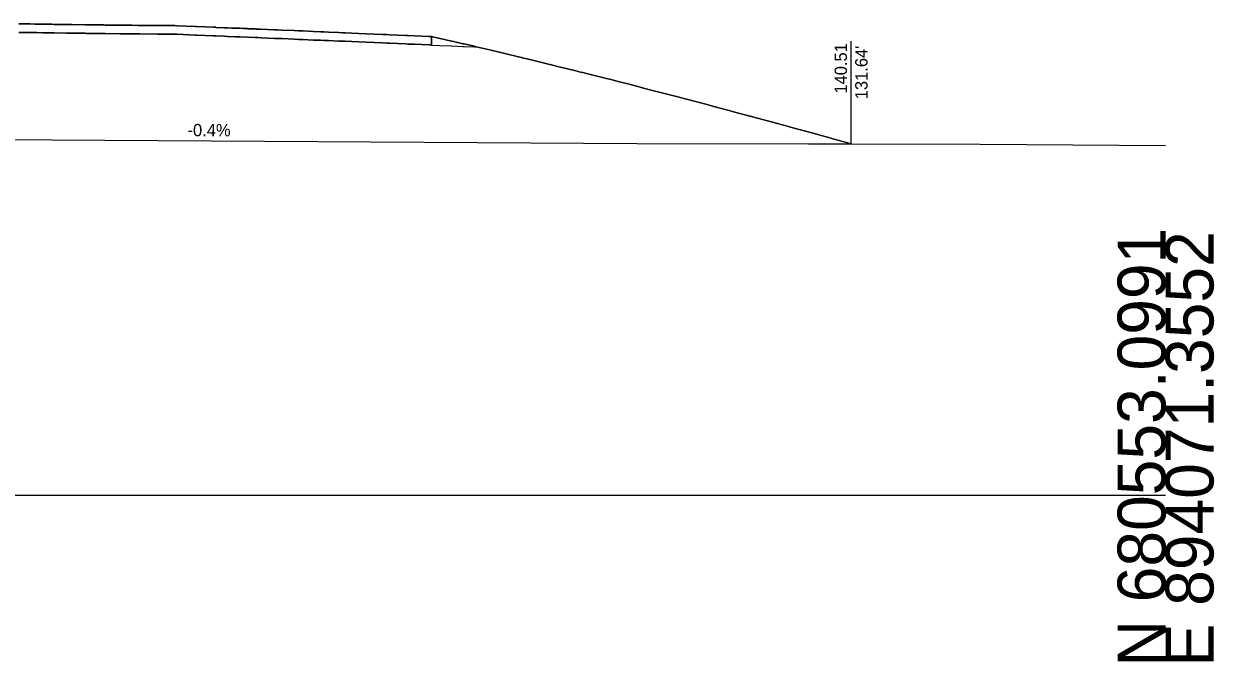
# Model space of a CAD drawing. Extents: x -26 to 4403, y -13 to 9578.
# Drawn here: x 1333.4 to 1402.8, y 7490.3 to 7527.5 of the extents above; entities that cross this region are included whole.
import ezdxf

# ---------------------------------------------------------------- set-up
doc = ezdxf.new("R2010")
doc.units = 0
for name, color, linetype in [('CONST_LV3', 7, 'Continuous'), ('DTM_P_FINISHED_GRADE', 7, 'Continuous'), ('DTM_X_GROUND', 7, 'Continuous'), ('X_PROFILES_1', 7, 'Continuous'), ('XS_CELL', 7, 'Continuous'), ('XS_M_SHAPES_EARTHWORK', 7, 'Continuous'), ('XS_P_DR_GRAVEL', 7, 'Continuous'), ('XS_P_GROUND', 7, 'Continuous'), ('XS_P_TX_CLEARZONE', 7, 'Continuous'), ('XS_P_TX_FS_BS', 7, 'Continuous')]:
    doc.layers.add(name, color=color, linetype=linetype)

msp = doc.modelspace()

# ---------------------------------------------------------------- linework, layer by layer
at = {"layer": 'CONST_LV3'}
msp.add_lwpolyline([(1333.065, 7527.511), (1333.712, 7527.501), (1333.992, 7527.496), (1334.096, 7527.494), (1334.782, 7527.485), (1334.979, 7527.481), (1335.338, 7527.477), (1335.483, 7527.474), (1335.854, 7527.469), (1335.978, 7527.467), (1336.156, 7527.464), (1336.927, 7527.455), (1336.991, 7527.454), (1337.184, 7527.451), (1338, 7527.442), (1338.018, 7527.442), (1338.107, 7527.44), (1338.989, 7527.431), (1339.061, 7527.43), (1339.075, 7527.43), (1340.031, 7527.421), (1340.131, 7527.42), (1340.148, 7527.42), (1340.642, 7527.415), (1340.7, 7527.415), (1341.204, 7527.411), (1341.221, 7527.411), (1342.167, 7527.404), (1342.294, 7527.399), (1342.297, 7527.399), (1342.298, 7527.398), (1342.301, 7527.398), (1343.364, 7527.354), (1343.416, 7527.352), (1343.438, 7527.352), (1344.433, 7527.31), (1344.558, 7527.305), (1344.576, 7527.305), (1345.5, 7527.266), (1345.715, 7527.257), (1345.724, 7527.257), (1346.164, 7527.238), (1346.423, 7527.227), (1346.853, 7527.209), (1346.915, 7527.207), (1347.013, 7527.203), (1347.186, 7527.196), (1347.991, 7527.161), (1348.135, 7527.155), (1348.413, 7527.144), (1349.128, 7527.113), (1349.384, 7527.103), (1349.641, 7527.092), (1350.264, 7527.065), (1350.665, 7527.048), (1350.872, 7527.04), (1351.398, 7527.017), (1351.981, 7526.993), (1352.103, 7526.988), (1352.326, 7526.978), (1352.719, 7526.962), (1352.915, 7526.953), (1353.333, 7526.935), (1354.298, 7526.893), (1354.566, 7526.881), (1354.725, 7526.876), (1355.655, 7526.835), (1355.797, 7526.829), (1356.159, 7526.814), (1357.015, 7526.777), (1357.028, 7526.776), (1357.154, 7526.771)], dxfattribs=at)
at = {"layer": 'DTM_P_FINISHED_GRADE'}
msp.add_lwpolyline([(1333.067, 7527.511), (1333.712, 7527.501), (1333.992, 7527.496), (1333.995, 7527.496), (1334.099, 7527.494), (1334.435, 7527.489), (1334.636, 7527.486), (1334.979, 7527.481), (1334.982, 7527.481), (1335.129, 7527.479), (1335.854, 7527.469), (1335.978, 7527.467), (1335.981, 7527.467), (1336.159, 7527.464), (1336.927, 7527.455), (1336.991, 7527.454), (1336.994, 7527.454), (1337.187, 7527.451), (1338.001, 7527.442), (1338.018, 7527.442), (1338.022, 7527.442), (1338.111, 7527.44), (1338.989, 7527.431), (1339.061, 7527.43), (1339.065, 7527.43), (1339.078, 7527.43), (1339.544, 7527.425), (1339.662, 7527.424), (1340.131, 7527.42), (1340.134, 7527.42), (1340.152, 7527.42), (1341.165, 7527.411), (1341.204, 7527.411), (1341.208, 7527.411), (1341.225, 7527.411), (1342.167, 7527.404), (1342.294, 7527.399), (1342.297, 7527.399), (1342.298, 7527.398), (1342.302, 7527.398), (1342.305, 7527.398), (1343.364, 7527.354), (1343.417, 7527.352), (1343.42, 7527.352), (1343.442, 7527.351), (1344.433, 7527.31), (1344.558, 7527.305), (1344.562, 7527.305), (1344.58, 7527.304), (1345.057, 7527.284), (1345.248, 7527.277), (1345.715, 7527.257), (1345.724, 7527.257), (1345.727, 7527.256), (1345.965, 7527.247), (1346.853, 7527.209), (1346.915, 7527.207), (1346.919, 7527.207), (1347.017, 7527.203), (1347.189, 7527.195), (1347.991, 7527.161), (1348.135, 7527.155), (1348.138, 7527.155), (1348.416, 7527.144), (1349.128, 7527.113), (1349.384, 7527.103), (1349.387, 7527.103), (1349.644, 7527.092), (1350.264, 7527.065), (1350.665, 7527.048), (1350.668, 7527.048), (1350.874, 7527.04), (1351.148, 7527.028), (1351.738, 7527.003), (1351.981, 7526.993), (1351.983, 7526.992), (1352.105, 7526.988), (1352.505, 7526.971), (1352.915, 7526.953), (1353.333, 7526.935), (1353.335, 7526.935), (1354.299, 7526.893), (1354.566, 7526.881), (1354.725, 7526.876), (1354.726, 7526.875), (1355.655, 7526.835), (1355.797, 7526.829), (1356.159, 7526.814), (1356.159, 7526.814), (1357.015, 7526.777), (1357.028, 7526.776), (1357.154, 7526.771)], dxfattribs=at)
at = {"layer": 'DTM_X_GROUND'}
msp.add_lwpolyline([(1159.518, 7517.394), (1200.052, 7515.401), (1217.74, 7513.76), (1222.892, 7513.417), (1226.763, 7513.627), (1241.699, 7515.779), (1244.696, 7517.139), (1249.906, 7516.828), (1249.956, 7516.833), (1276.709, 7519.611), (1283.124, 7519.79), (1294.202, 7520.766), (1295.632, 7520.835), (1310.279, 7520.767), (1331.863, 7520.749), (1369.14, 7520.527), (1389.173, 7520.495), (1400, 7520.407)], dxfattribs=at)
at = {"layer": 'XS_CELL'}
msp.add_line((1250, 7500), (1400, 7500), dxfattribs=at)
at = {"layer": 'XS_M_SHAPES_EARTHWORK'}
msp.add_lwpolyline([(1331.863, 7520.749), (1369.14, 7520.527), (1381.644, 7520.507), (1380.44, 7520.839), (1380.41, 7520.848), (1379.765, 7521.027), (1379.638, 7521.062), (1378.027, 7521.502), (1377.985, 7521.513), (1377.708, 7521.589), (1377.423, 7521.667), (1375.888, 7522.083), (1375.77, 7522.114), (1375.737, 7522.122), (1375.52, 7522.182), (1374.782, 7522.38), (1374.533, 7522.448), (1373.848, 7522.631), (1373.741, 7522.658), (1373.697, 7522.67), (1373.161, 7522.813), (1372.033, 7523.11), (1371.874, 7523.152), (1371.605, 7523.222), (1371.071, 7523.362), (1370.287, 7523.565), (1369.982, 7523.645), (1369.605, 7523.741), (1369.122, 7523.866), (1368.607, 7523.998), (1368.125, 7524.121), (1367.69, 7524.232), (1367.296, 7524.331), (1366.986, 7524.409), (1366.519, 7524.528), (1366.197, 7524.608), (1365.985, 7524.662), (1365.852, 7524.695), (1365.581, 7524.762), (1365.422, 7524.801), (1364.516, 7525.027), (1364.086, 7525.132), (1364.033, 7525.145), (1363.91, 7525.174), (1362.809, 7525.445), (1362.446, 7525.533), (1362.432, 7525.536), (1362.387, 7525.546), (1361.275, 7525.815), (1361.029, 7525.873), (1360.699, 7525.949), (1360.638, 7525.963), (1359.768, 7526.17), (1359.654, 7526.197), (1359.112, 7526.321), (1359.06, 7526.333), (1358.988, 7526.349), (1358.982, 7526.351), (1358.355, 7526.498), (1358.32, 7526.506), (1357.654, 7526.658), (1357.639, 7526.662), (1357.154, 7526.771), (1357.154, 7526.271), (1357.028, 7526.276), (1357.015, 7526.277), (1356.159, 7526.314), (1355.797, 7526.329), (1355.655, 7526.335), (1354.725, 7526.376), (1354.566, 7526.381), (1354.299, 7526.393), (1353.335, 7526.435), (1353.333, 7526.435), (1352.915, 7526.453), (1352.505, 7526.471), (1352.105, 7526.488), (1351.983, 7526.492), (1351.981, 7526.493), (1351.738, 7526.503), (1351.148, 7526.528), (1350.874, 7526.54), (1350.668, 7526.548), (1350.665, 7526.548), (1350.264, 7526.565), (1349.644, 7526.592), (1349.387, 7526.603), (1349.384, 7526.603), (1349.128, 7526.613), (1348.416, 7526.644), (1348.138, 7526.655), (1348.135, 7526.655), (1347.991, 7526.661), (1347.189, 7526.695), (1347.017, 7526.703), (1346.919, 7526.707), (1346.915, 7526.707), (1346.853, 7526.709), (1345.965, 7526.747), (1345.727, 7526.756), (1345.724, 7526.757), (1345.715, 7526.757), (1345.248, 7526.777), (1345.057, 7526.784), (1344.58, 7526.804), (1344.562, 7526.805), (1344.558, 7526.805), (1344.433, 7526.81), (1343.442, 7526.851), (1343.42, 7526.852), (1343.417, 7526.852), (1343.364, 7526.854), (1342.305, 7526.898), (1342.302, 7526.898), (1342.297, 7526.899), (1342.294, 7526.899), (1342.167, 7526.904), (1341.225, 7526.911), (1341.208, 7526.911), (1341.204, 7526.911), (1341.165, 7526.911), (1340.152, 7526.92), (1340.134, 7526.92), (1340.131, 7526.92), (1339.662, 7526.924), (1339.544, 7526.925), (1339.078, 7526.93), (1339.065, 7526.93), (1339.061, 7526.93), (1338.989, 7526.931), (1338.111, 7526.94), (1338.022, 7526.942), (1338.018, 7526.942), (1338.001, 7526.942), (1337.187, 7526.951), (1336.994, 7526.954), (1336.991, 7526.954), (1336.927, 7526.955), (1336.159, 7526.964), (1335.981, 7526.967), (1335.978, 7526.967), (1335.854, 7526.969), (1335.129, 7526.979), (1334.982, 7526.981), (1334.979, 7526.981), (1334.636, 7526.986), (1334.435, 7526.989), (1334.099, 7526.994), (1333.995, 7526.996), (1333.992, 7526.996), (1333.712, 7527.001), (1333.067, 7527.011)], dxfattribs=at)
at = {"layer": 'XS_P_DR_GRAVEL'}
for points in [[(1333.067, 7527.011), (1333.712, 7527.001), (1333.992, 7526.996), (1333.995, 7526.996), (1334.099, 7526.994), (1334.435, 7526.989), (1334.636, 7526.986), (1334.979, 7526.981), (1334.982, 7526.981), (1335.129, 7526.979), (1335.854, 7526.969), (1335.978, 7526.967), (1335.981, 7526.967), (1336.159, 7526.964), (1336.927, 7526.955), (1336.991, 7526.954), (1336.994, 7526.954), (1337.187, 7526.951), (1338.001, 7526.942), (1338.018, 7526.942), (1338.022, 7526.942), (1338.111, 7526.94), (1338.989, 7526.931), (1339.061, 7526.93), (1339.065, 7526.93), (1339.078, 7526.93), (1339.544, 7526.925), (1339.662, 7526.924), (1340.131, 7526.92), (1340.134, 7526.92), (1340.152, 7526.92), (1341.165, 7526.911), (1341.204, 7526.911), (1341.208, 7526.911), (1341.225, 7526.911), (1342.167, 7526.904), (1342.294, 7526.899), (1342.297, 7526.899), (1342.298, 7526.898), (1342.302, 7526.898), (1342.305, 7526.898), (1343.364, 7526.854), (1343.417, 7526.852), (1343.42, 7526.852), (1343.442, 7526.851), (1344.433, 7526.81), (1344.558, 7526.805), (1344.562, 7526.805), (1344.58, 7526.804), (1345.057, 7526.784), (1345.248, 7526.777), (1345.715, 7526.757), (1345.724, 7526.757), (1345.727, 7526.756), (1345.965, 7526.747), (1346.853, 7526.709), (1346.915, 7526.707), (1346.919, 7526.707), (1347.017, 7526.703), (1347.189, 7526.695), (1347.991, 7526.661), (1348.135, 7526.655), (1348.138, 7526.655), (1348.416, 7526.644), (1349.128, 7526.613), (1349.384, 7526.603), (1349.387, 7526.603), (1349.644, 7526.592), (1350.264, 7526.565), (1350.665, 7526.548), (1350.668, 7526.548), (1350.874, 7526.54), (1351.148, 7526.528), (1351.738, 7526.503), (1351.981, 7526.493), (1351.983, 7526.492), (1352.105, 7526.488), (1352.505, 7526.471), (1352.915, 7526.453), (1353.333, 7526.435), (1353.335, 7526.435), (1354.299, 7526.393), (1354.566, 7526.381), (1354.725, 7526.376), (1354.726, 7526.375), (1355.655, 7526.335), (1355.797, 7526.329), (1356.159, 7526.314), (1356.159, 7526.314), (1357.015, 7526.277), (1357.028, 7526.276), (1357.154, 7526.271), (1357.154, 7526.771), (1357.028, 7526.776), (1357.015, 7526.777), (1356.159, 7526.814), (1356.159, 7526.814), (1355.797, 7526.829), (1355.655, 7526.835), (1354.726, 7526.875), (1354.725, 7526.876), (1354.566, 7526.881), (1354.299, 7526.893), (1353.335, 7526.935), (1353.333, 7526.935), (1352.915, 7526.953), (1352.505, 7526.971), (1352.105, 7526.988), (1351.983, 7526.992), (1351.981, 7526.993), (1351.738, 7527.003), (1351.148, 7527.028), (1350.874, 7527.04), (1350.668, 7527.048), (1350.665, 7527.048), (1350.264, 7527.065), (1349.644, 7527.092), (1349.387, 7527.103), (1349.384, 7527.103), (1349.128, 7527.113), (1348.416, 7527.144), (1348.138, 7527.155), (1348.135, 7527.155), (1347.991, 7527.161), (1347.189, 7527.195), (1347.017, 7527.203), (1346.919, 7527.207), (1346.915, 7527.207), (1346.853, 7527.209), (1345.965, 7527.247), (1345.727, 7527.256), (1345.724, 7527.257), (1345.715, 7527.257), (1345.248, 7527.277), (1345.057, 7527.284), (1344.58, 7527.304), (1344.562, 7527.305), (1344.558, 7527.305), (1344.433, 7527.31), (1343.442, 7527.351), (1343.42, 7527.352), (1343.417, 7527.352), (1343.364, 7527.354), (1342.305, 7527.398), (1342.302, 7527.398), (1342.298, 7527.398), (1342.297, 7527.399), (1342.294, 7527.399), (1342.167, 7527.404), (1341.225, 7527.411), (1341.208, 7527.411), (1341.204, 7527.411), (1341.165, 7527.411), (1340.152, 7527.42), (1340.134, 7527.42), (1340.131, 7527.42), (1339.662, 7527.424), (1339.544, 7527.425), (1339.078, 7527.43), (1339.065, 7527.43), (1339.061, 7527.43), (1338.989, 7527.431), (1338.111, 7527.44), (1338.022, 7527.442), (1338.018, 7527.442), (1338.001, 7527.442), (1337.187, 7527.451), (1336.994, 7527.454), (1336.991, 7527.454), (1336.927, 7527.455), (1336.159, 7527.464), (1335.981, 7527.467), (1335.978, 7527.467), (1335.854, 7527.469), (1335.129, 7527.479), (1334.982, 7527.481), (1334.979, 7527.481), (1334.636, 7527.486), (1334.435, 7527.489), (1334.099, 7527.494), (1333.995, 7527.496), (1333.992, 7527.496), (1333.712, 7527.501), (1333.067, 7527.511)], [(1357.154, 7526.271), (1357.639, 7526.251), (1358.32, 7526.222), (1358.982, 7526.192), (1359.06, 7526.188), (1359.654, 7526.165), (1359.818, 7526.158)]]:
    msp.add_lwpolyline(points, dxfattribs=at)
at = {"layer": 'XS_P_GROUND'}
msp.add_lwpolyline([(1357.154, 7526.771), (1357.639, 7526.662), (1357.654, 7526.658), (1358.32, 7526.506), (1358.355, 7526.498), (1358.982, 7526.351), (1358.988, 7526.349), (1359.06, 7526.333), (1359.112, 7526.321), (1359.654, 7526.197), (1359.768, 7526.17), (1360.638, 7525.963), (1360.699, 7525.949), (1361.029, 7525.873), (1361.275, 7525.815), (1362.387, 7525.546), (1362.432, 7525.536), (1362.446, 7525.533), (1362.809, 7525.445), (1363.91, 7525.174), (1364.033, 7525.145), (1364.086, 7525.132), (1364.516, 7525.027), (1365.422, 7524.801), (1365.581, 7524.762), (1365.852, 7524.695), (1365.985, 7524.662), (1366.197, 7524.608), (1366.519, 7524.528), (1366.986, 7524.409), (1367.296, 7524.331), (1367.69, 7524.232), (1368.125, 7524.121), (1368.607, 7523.998), (1369.122, 7523.866), (1369.605, 7523.741), (1369.982, 7523.645), (1370.287, 7523.565), (1371.071, 7523.362), (1371.605, 7523.222), (1371.874, 7523.152), (1372.033, 7523.11), (1373.161, 7522.813), (1373.697, 7522.67), (1373.741, 7522.658), (1373.848, 7522.631), (1374.533, 7522.448), (1374.782, 7522.38), (1375.52, 7522.182), (1375.737, 7522.122), (1375.77, 7522.114), (1375.888, 7522.083), (1377.423, 7521.667), (1377.708, 7521.589), (1377.985, 7521.513), (1378.027, 7521.502), (1379.638, 7521.062), (1379.765, 7521.027), (1380.41, 7520.848), (1380.44, 7520.839), (1381.644, 7520.507)], dxfattribs=at)
at = {"layer": 'XS_P_TX_CLEARZONE'}
msp.add_line((1381.644, 7520.507), (1381.644, 7526.507), dxfattribs=at)
msp.add_line((1381.644, 7520.507), (1381.644, 7526.507), dxfattribs=at)
msp.add_line((1381.644, 7520.507), (1381.644, 7526.507), dxfattribs=at)
msp.add_line((1381.644, 7520.507), (1381.644, 7526.507), dxfattribs=at)
msp.add_line((1381.644, 7520.507), (1381.644, 7526.507), dxfattribs=at)
msp.add_line((1381.644, 7520.507), (1381.644, 7526.507), dxfattribs=at)

# ---------------------------------------------------------------- texts
at = {"layer": 'X_PROFILES_1'}
msp.add_text('X', height=0.12, dxfattribs=at).set_placement((1381.605, 7520.447))
at = {"layer": 'XS_CELL'}
for s, p in [('N 680553.0991', (1400, 7490)), ('E 894071.3552', (1402.8, 7490))]:
    msp.add_text(s, height=2.8, rotation=90, dxfattribs=at).set_placement(p)
at = {"layer": 'XS_P_TX_CLEARZONE'}
for s, p in [('140.51', (1381.404, 7523.436)), ('140.51', (1381.404, 7523.436)), ('140.51', (1381.404, 7523.436)), ('140.51', (1381.404, 7523.436)), ('140.51', (1381.404, 7523.436)), ('140.51', (1381.404, 7523.436)), ("131.64'", (1382.604, 7523.107)), ("131.64'", (1382.604, 7523.107)), ("131.64'", (1382.604, 7523.107)), ("131.64'", (1382.604, 7523.107)), ("131.64'", (1382.604, 7523.107)), ("131.64'", (1382.604, 7523.107))]:
    msp.add_text(s, height=0.72, rotation=90, dxfattribs=at).set_placement(p)
at = {"layer": 'XS_P_TX_FS_BS'}
msp.add_text('-0.4%', height=0.72, rotation=359.78825, dxfattribs=at).set_placement((1342.909, 7520.95))
msp.add_text('-0.4%', height=0.72, rotation=359.78825, dxfattribs=at).set_placement((1342.909, 7520.95))
msp.add_text('-0.4%', height=0.72, rotation=359.78825, dxfattribs=at).set_placement((1342.909, 7520.95))

doc.saveas('drawing.dxf')
